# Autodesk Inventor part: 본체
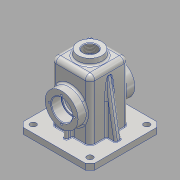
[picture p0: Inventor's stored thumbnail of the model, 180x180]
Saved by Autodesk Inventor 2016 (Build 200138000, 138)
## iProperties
Created: 2018-10
Part Number: 본체
Material: 알루미늄 6061
Document SubType Name: Modeling
Designer: user
Density: 2.7 g/cm^3
Appearance: 알루미늄 - 평지
Mass: 794.227 g
Surface Area: 899.5 cm^2
Volume: 294.158 cm^3
Author: user
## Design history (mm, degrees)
sketch "스케치1"
  geometry: L1 (-60, -60)-(60, -60); L2 (60, -60)-(60, 60); L3 (60, 60)-(-60, 60); L4 (-60, 60)-(-60, -60); L5 (-60, -60)-(60, 60); L6 (60, -60)-(-60, 60); 1 further point
  constraints: 12 end point, 2 midpoint, 2 parallel, 1 horizontal, 1 perpendicular
  dimensions: "d0" = 120 distance of L3.end L2.end; "d1" = 120 distance of L2.end L1.end
extrude "돌출1" new body sketch "스케치1" distance "d2" = 10; taper "d3" = 0 deg
sketch "스케치2"
  geometry: L1 (-32.5, -32.5)-(32.5, -32.5); L2 (32.5, -32.5)-(32.5, 32.5); L3 (32.5, 32.5)-(-32.5, 32.5); L4 (-32.5, 32.5)-(-32.5, -32.5); L5 (-32.5, -32.5)-(32.5, 32.5); L6 (32.5, -32.5)-(-32.5, 32.5); 1 further point
  constraints: 12 end point, 2 midpoint, 2 parallel, 1 horizontal, 1 perpendicular
  dimensions: "d4" = 65 distance of L3.end L2.end; "d5" = 65 distance of L2.end L1.end
extrude "돌출2" join sketch "스케치2" distance "d6" = 100; taper "d7" = 0 deg
fillet "모깎기1" dims "d8" = 8
fillet "모깎기2" dims "d9" = 8
feature "쉘1" dims "d10" = 10, "d11" = 5
sketch "스케치3"
  geometry: L1 (84.5, 0)-(84.5, -10) reference; L2 (84.5, -10)-(-35.5, -10) reference; L3 (-35.5, -10)-(-35.5, 0) reference; L4 (-35.5, 0)-(0, 0) reference; L5 (0, 0)-(49, 0) reference; L6 (49, 0)-(84.5, 0) reference; L7 (0, 0)-(0, 92) reference; L8 (0, 92)-(49, 92) reference; L9 (49, 0)-(49, 92) reference; L10 (-35.5, -10)-(84.5, -10) reference; C1 r 27.5 at (24.5, 45); 2 further points
  constraints: 1 centre point, 1 midpoint, 1 vertical alignment
  dimensions: "d12" = 55 diameter of C1; "d13" = 55 distance from line of C1.centre L2
extrude "돌출3" join sketch "스케치3" distance "d14" = 15; taper "d15" = 0 deg
hole "구멍1" diameter "d18" = 30; stored, may be unused: countersink angle "d22" = 90 deg, drill point angle "d24" = 118 deg; dims "d16" = 10, "d17" = 10, "d19" = 6, "d20" = 35, "d21" = 17, "d23" = 8
sketch "스케치4"
  geometry: L1 (60, -45)-(60, -55) reference; L2 (60, -55)-(-60, -55) reference; L3 (-60, -55)-(-60, -45) reference; L4 (-60, -45)-(60, -45) reference; C1 r 17.5 at (0, 0) reference; C2 r 27.5 at (0, 0) reference; 2 further points
  constraints: 1 vertical alignment
  dimensions: "d25" = 21 distance of point (0, 21) C1.centre
hole "구멍2" sketch "스케치4" at (0, 21) diameter "d26" = 3.242; stored, may be unused: countersink angle "d30" = 90 deg, drill point angle "d32" = 118 deg; dims "d27" = 8, "d28" = 35, "d29" = 17, "d31" = 10
sketch "스케치5"
  geometry: L1 (-32.5, 27.5)-(-47.5, 27.5) reference; L2 (-42.5, 27.5)-(-42.5, 10.398); L3 (60, 10)-(-60, 10) reference; L4 (-27.5, 0)-(-27.5, 102) reference; 1 further point
  constraints: 2 end point, 1 perpendicular, 1 point on line
  dimensions: "d36" = 15 distance between parallel lines of L2 L4
feature "리브1" sketch "스케치5" dims "d37" = 1, "d38" = 6, "d39" = 0, "d40" = 0, "d41" = 1, "d42" = 1
node "작업 평면1"
sketch "스케치8"
  geometry: C1 r 20 at (0, 0); 1 further point
  constraints: 1 centre point, 1 coincident
  dimensions: "d54" = 40 diameter of C1
extrude "돌출4" join sketch "스케치8" stored distance "d55" = 10; taper "d56" = 7 deg
hole "구멍4" diameter "d59" = 22.835; stored, may be unused: countersink angle "d63" = 90 deg, drill point angle "d65" = 118 deg; dims "d57" = 10, "d58" = 10, "d60" = 50, "d61" = 4, "d62" = 2, "d64" = 59.3
sketch "스케치9"
  geometry: L1 (60, 0)-(27.5, 0) reference; L2 (27.5, 0)-(27.5, 102) reference; L3 (24.5, 105)-(11.418, 105) reference; L4 (11.418, 105)-(11.418, 120) reference; L5 (11.418, 120)-(20, 120) reference; L6 (20, 120)-(21.228, 110) reference; L7 (21.228, 110)-(24.5, 110) reference; L8 (32.5, 102)-(32.5, 10) reference; L9 (32.5, 10)-(60, 10) reference; L10 (60, 10)-(60, 0) reference; L11 (-27.5, 0)-(-60, 0) reference; L12 (-60, 0)-(-60, 10) reference; L13 (-60, 10)-(-32.5, 10) reference; L14 (-32.5, 10)-(-32.5, 102) reference; L15 (-24.5, 110)-(-21.228, 110) reference; L16 (-21.228, 110)-(-20, 120) reference; L17 (-20, 120)-(-11.418, 120) reference; L18 (-11.418, 120)-(-11.418, 105) reference; L19 (-11.418, 105)-(-24.5, 105) reference; L20 (-27.5, 102)-(-27.5, 0) reference; L21 (-60, 10)-(60, 10) reference; L22 (48, 10)-(32.5, 97.905); L23 (32.5, 10)-(32.5, 102) reference; A1 r 3 centre (24.5, 102) between (27.5, 102) and (24.5, 105) reference; A2 r 8 centre (24.5, 102) between (32.5, 102) and (24.5, 110) reference; A3 r 8 centre (-24.5, 102) between (-24.5, 110) and (-32.5, 102) reference; A4 r 3 centre (-24.5, 102) between (-24.5, 105) and (-27.5, 102) reference; 1 further point
  constraints: 2 end point, 2 point on line
  dimensions: "d66" = 12 distance from line of L22.start L10; "d67" = 10 deg angle of L22 L10
feature "리브2" sketch "스케치9" dims "d68" = 1, "d69" = 10, "d70" = 0, "d71" = 0, "d72" = 1, "d73" = 1
sketch "스케치6"
  geometry: L1 (3, -32.5)-(3, -42.5) reference; L2 (3, -42.5)-(-3, -42.5) reference; L3 (-3, -42.5)-(-3, -32.5) reference; L4 (-3, -32.5)-(-24.5, -32.5) reference; L5 (-32.5, -24.5)-(-32.5, -5) reference; L6 (-24.5, 32.5)-(-3, 32.5) reference; L7 (-3, 32.5)-(-3, 42.5) reference; L8 (-3, 42.5)-(3, 42.5) reference; L9 (3, 42.5)-(3, 32.5) reference; L10 (3, 32.5)-(24.5, 32.5) reference; L11 (32.5, 24.5)-(32.5, 5) reference; L12 (24.5, -32.5)-(3, -32.5) reference; L13 (24.5, 27.5)-(-24.5, 27.5) reference; L14 (-27.5, 24.5)-(-27.5, -24.5) reference; L15 (-24.5, -27.5)-(24.5, -27.5) reference; L16 (27.5, -24.5)-(27.5, 24.5) reference; L17 (-60, 60)-(60, 60) reference; L18 (60, 60)-(60, -60) reference; L19 (60, -60)-(-60, -60) reference; L20 (-60, -60)-(-60, 60) reference; L21 (47.5, -47.5)-(-47.5, -47.5); L22 (-47.5, -47.5)-(-47.5, 47.5); L23 (-47.5, 47.5)-(47.5, 47.5); L24 (47.5, 47.5)-(47.5, -47.5); L25 (47.5, -47.5)-(-47.5, 47.5); L26 (-47.5, -47.5)-(47.5, 47.5); L27 (-32.5, -5)-(-48, -5) reference; L28 (-48, -5)-(-48, 5) reference; L29 (-48, 5)-(-32.5, 5) reference; L30 (-32.5, 5)-(-32.5, 24.5) reference; L31 (32.5, 5)-(48, 5) reference; L32 (48, 5)-(48, -5) reference; L33 (48, -5)-(32.5, -5) reference; L34 (32.5, -5)-(32.5, -24.5) reference; A1 r 8 centre (-24.5, -24.5) between (-32.5, -24.5) and (-24.5, -32.5) reference; A2 r 8 centre (-24.5, 24.5) between (-24.5, 32.5) and (-32.5, 24.5) reference; A3 r 8 centre (24.5, 24.5) between (32.5, 24.5) and (24.5, 32.5) reference; A4 r 8 centre (24.5, -24.5) between (24.5, -32.5) and (32.5, -24.5) reference; A5 r 3 centre (-24.5, 24.5) between (-24.5, 27.5) and (-27.5, 24.5) reference; A6 r 3 centre (-24.5, -24.5) between (-27.5, -24.5) and (-24.5, -27.5) reference; A7 r 3 centre (24.5, -24.5) between (24.5, -27.5) and (27.5, -24.5) reference; A8 r 3 centre (24.5, 24.5) between (27.5, 24.5) and (24.5, 27.5) reference; 5 further points
  constraints: 12 end point, 4 coincident, 2 midpoint, 2 parallel, 1 horizontal, 1 perpendicular
  dimensions: "d43" = 95 distance of L22.end L23.end; "d44" = 95 distance of L21.end L22.end
hole "구멍3" sketch "스케치6" at (-47.5, -47.5), (-47.5, 47.5), (47.5, 47.5), (47.5, -47.5) diameter "d45" = 10; stored, may be unused: countersink angle "d49" = 90 deg, drill point angle "d51" = 118 deg; dims "d46" = 6, "d47" = 4, "d48" = 2, "d50" = 8
chamfer "모따기1" distance "d74" = 8; stored, may be unused: second distance "d75" = 2, angle "d76" = 45 deg
fillet "모깎기3" dims "d77" = 3
fillet "모깎기4" dims "d78" = 1, "d79" = 3
chamfer "모따기2" distance "d80" = 1; stored, may be unused: second distance "d81" = 2, angle "d82" = 45 deg
fillet "모깎기5" dims "d83" = 0.3
sketch "스케치10"
  geometry: L1 (44.5, -18)-(4.5, -18) reference; L2 (57, 0)-(57, 91) reference; 2 further points
  constraints: 1 other
  dimensions: "d84" = 26 distance from line of point (24.5, 8) L1; "d85" = 32.5 distance from line of point (24.5, 8) L2
feature "엠보싱1" sketch "스케치10" dims "d0" = 120, "d1" = 120, "d86" = 0.5, "d87" = 0
node "솔리드1"
pattern_circular "원형 패턴1" dims angle "d34" = 360 deg
mirror "대칭1"
mirror "대칭2"
node "절단 모서리 투영1"
node "절단 모서리 투영2"
node "절단 모서리 투영3"
node "절단 모서리 투영4"
